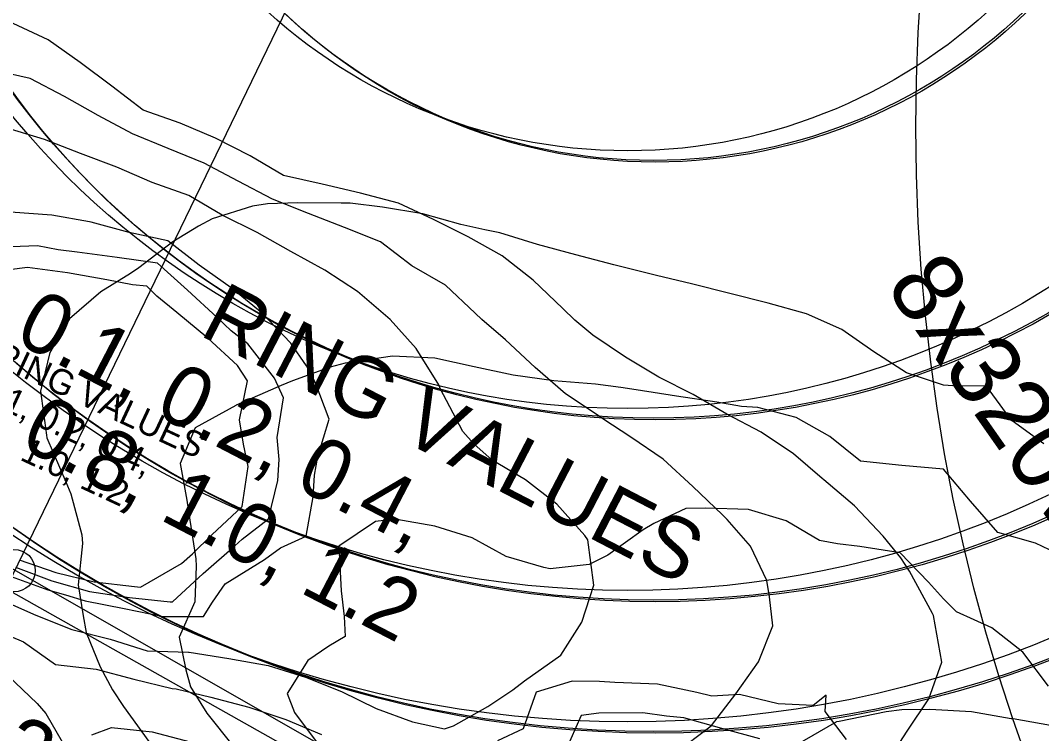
# Model space of a CAD drawing. Extents: x 1638506 to 1658005, y 834807 to 846788.
# Drawn here: x 1640509.7 to 1640711.8, y 842395.5 to 842536.6 of the extents above; entities that cross this region are included whole.
import ezdxf

# ---------------------------------------------------------------- set-up
doc = ezdxf.new("R2010")
doc.units = 0
for name, color, linetype in [('Default', 7, 'Continuous'), ('Old_Level_1', 7, 'Continuous'), ('Old_Level_2', 7, 'Continuous'), ('Old_Level_4', 7, 'Continuous'), ('Scratch_Level_0', 7, 'Continuous')]:
    doc.layers.add(name, color=color, linetype=linetype)

msp = doc.modelspace()

# ---------------------------------------------------------------- linework, layer by layer
at = {"layer": 'Default'}
msp.add_line((1640314.09, 842532.64), (1640637.56, 842350.59), dxfattribs=at)
at = {"layer": 'Old_Level_1'}
for points in [[(1640690.42, 842418.82), (1640690.18, 842419.27), (1640685.65, 842427.64), (1640683.96, 842430.27), (1640680.43, 842434.55), (1640674.78, 842440.54), (1640668.73, 842445.67), (1640668.39, 842445.97), (1640662.68, 842450.81), (1640656.27, 842455.16), (1640649.49, 842458.72), (1640642.86, 842462.61), (1640636.02, 842466.03), (1640629.42, 842469.97), (1640623, 842474.32), (1640619.41, 842477.26), (1640617.03, 842479.62), (1640611.2, 842485.22), (1640605.01, 842490.04), (1640598.31, 842493.77), (1640591.47, 842497.21), (1640584.54, 842500.44), (1640577.02, 842502.42), (1640569.42, 842504.21), (1640561.76, 842505.89), (1640555.14, 842509.81), (1640548.33, 842513.31), (1640541.28, 842516.27), (1640534.02, 842518.82), (1640527.82, 842523.61), (1640521.55, 842528.28), (1640515.2, 842532.77), (1640508.27, 842536)], [(1640658.59, 842416.78), (1640657.93, 842422.52), (1640657.41, 842425.77), (1640654.18, 842432.56), (1640649.57, 842437.87), (1640648.63, 842438.76), (1640642.79, 842444.36), (1640636.9, 842449.81), (1640630.48, 842454.15), (1640624.95, 842457.79), (1640624.03, 842458.42), (1640617.59, 842462.72), (1640611.58, 842467.93), (1640605.69, 842473.4), (1640601.01, 842477.39), (1640599.7, 842478.65), (1640593.84, 842484.19), (1640587.19, 842488.03), (1640580.96, 842492.76), (1640573.86, 842495.65), (1640566.71, 842498.42), (1640559.59, 842501.25), (1640552.79, 842504.77), (1640546.03, 842508.36), (1640538.93, 842511.24), (1640531.86, 842514.18), (1640525.11, 842517.82), (1640518.4, 842521.52), (1640511.62, 842525.09), (1640503.99, 842526.83)], [(1640621.97, 842433.85), (1640621.39, 842434.65), (1640615.86, 842440.9), (1640609.66, 842445.7), (1640603.04, 842449.61), (1640599.43, 842452.81), (1640597.25, 842455.28), (1640592.75, 842463.75), (1640592.51, 842464.47), (1640588.01, 842471.69), (1640582.88, 842477.41), (1640582.42, 842477.8), (1640576.39, 842482.97), (1640569.91, 842487.17), (1640563.21, 842490.9), (1640556.52, 842494.66), (1640549.65, 842498.04), (1640543.03, 842501.94), (1640535.79, 842504.5), (1640528.79, 842507.59), (1640521.61, 842510.3), (1640514.44, 842513.03), (1640507.06, 842515.3)], [(1640567.65, 842442.3), (1640567.88, 842446.61), (1640568.59, 842450.31), (1640570.82, 842457.71), (1640568.02, 842465.02), (1640566.31, 842468.25), (1640563.2, 842472.77), (1640557.51, 842478.68), (1640551.69, 842483.51), (1640551.42, 842483.72), (1640545.06, 842488.18), (1640538.85, 842492.96), (1640531.19, 842494.64), (1640523.68, 842496.65), (1640523.35, 842496.72), (1640515.91, 842498.08), (1640507.73, 842498.64)], [(1640560.65, 842445.57), (1640560.89, 842449.73), (1640560.48, 842454.09), (1640561.76, 842461.93), (1640559.96, 842465.83), (1640554.68, 842472.6), (1640551.43, 842475.19), (1640548.66, 842477.8), (1640542.74, 842483.2), (1640536.81, 842488.6), (1640528.87, 842489.67), (1640520.93, 842490.73), (1640517.14, 842491.18), (1640513.08, 842492), (1640504.49, 842491.7)], [(1640554.76, 842448.31), (1640553.86, 842452.76), (1640553.04, 842457.56), (1640554.61, 842465.27), (1640552.67, 842468.29), (1640546.77, 842473.75), (1640540.68, 842478.79), (1640536.67, 842482.07), (1640534.69, 842484.05), (1640531.9, 842484.3), (1640526.81, 842485.26), (1640519.04, 842486.68), (1640511.07, 842487.69), (1640507.5, 842487.23)], [(1640406.77, 842463.14), (1640413.31, 842459.07), (1640420.1, 842455.53), (1640427.02, 842452.26), (1640434.01, 842449.16), (1640440.59, 842445.17), (1640447.25, 842441.34), (1640453.59, 842436.84), (1640456.26, 842435.16), (1640460.09, 842432.67), (1640466.44, 842428.18), (1640472.25, 842422.54), (1640473.61, 842418.63), (1640476.35, 842413.25), (1640482.75, 842414.37), (1640485.31, 842414.35), (1640493.33, 842413.46), (1640499.55, 842408.7), (1640507.2, 842407), (1640513.04, 842401.41), (1640514.7, 842399.47), (1640517.95, 842393.85)], [(1640509.43, 842429.87), (1640516.69, 842427.34), (1640524.27, 842425.51), (1640532.29, 842424.6), (1640533.47, 842424.48), (1640541.55, 842429.15), (1640543.75, 842431.07), (1640547.56, 842434.79), (1640553.56, 842440.43), (1640554.76, 842448.31)], [(1640508.75, 842428.43), (1640515.94, 842425.74), (1640523.39, 842423.61), (1640531.27, 842422.41), (1640539.31, 842421.54), (1640539.77, 842421.54), (1640545.86, 842427.14), (1640552.15, 842432.65), (1640553.55, 842433.98), (1640558.82, 842437.98), (1640560.65, 842445.57)], [(1640507.89, 842426.57), (1640515.1, 842423.94), (1640518.61, 842422.97), (1640522.51, 842421.72), (1640530.25, 842420.22), (1640537.97, 842418.67), (1640545.92, 842418.67), (1640547.74, 842421.52), (1640550.24, 842425.1), (1640558.03, 842429.91), (1640561.19, 842432.27), (1640566.25, 842434.52), (1640567.65, 842442.3)], [(1640505.77, 842422.02), (1640512.77, 842418.94), (1640519.88, 842416.08), (1640527.44, 842414.19), (1640534.79, 842411.86), (1640542.97, 842411.61), (1640543.11, 842411.59), (1640550.96, 842410.33), (1640558.76, 842408.95), (1640566.13, 842406.67), (1640573.25, 842403.83), (1640580.12, 842400.47), (1640587.32, 842397.8), (1640593.64, 842396.42), (1640595.39, 842397.01), (1640602.21, 842400.87), (1640607.16, 842404.14), (1640609.49, 842405.91), (1640616.62, 842411.03), (1640620.81, 842417.52), (1640623.21, 842424.84), (1640621.97, 842433.85)], [(1640680.97, 842389.46), (1640685.17, 842395.95), (1640689.51, 842402.36), (1640692.08, 842409.6), (1640690.42, 842418.82)], [(1640639.59, 842391.88), (1640645.86, 842396.62), (1640646.47, 842397.11), (1640651.25, 842403.32), (1640655.79, 842409.65), (1640658.59, 842416.78)], [(1640503.25, 842416.62), (1640510.3, 842413.65), (1640516.64, 842409.14), (1640524.66, 842408.24), (1640532.17, 842406.23), (1640539.75, 842404.4), (1640540.5, 842404.32), (1640547.39, 842402.66), (1640554.92, 842400.71), (1640562.22, 842398.28), (1640569.28, 842395.32)], [(1640713.56, 842397.1), (1640706.19, 842398.37), (1640705.74, 842398.43), (1640697.92, 842399.77), (1640689.7, 842400.25), (1640684.15, 842400.2), (1640681.05, 842399.81), (1640671.72, 842397.9), (1640671.23, 842397.79), (1640663.1, 842393.14)], [(1640523.84, 842395.21), (1640527.71, 842396.68), (1640535.77, 842395.85), (1640543.29, 842393.88)]]:
    msp.add_lwpolyline(points, dxfattribs=at)
for centre, radius in [((1640635.3, 842614.58), 219), ((1640635.3, 842614.58), 193), ((1640635.3, 842614.58), 157), ((1640635.3, 842614.58), 106), ((1640508.42, 842427.72), 4.21)]:
    msp.add_circle(centre, radius, dxfattribs=at)
at = {"layer": 'Old_Level_2'}
for p, q in [((1640570.5, 842555.69), (1640460.25, 842328.04)), ((1640394.38, 842493.02), (1640843.22, 842236.75))]:
    msp.add_line(p, q, dxfattribs=at)
at = {"layer": 'Old_Level_4'}
for centre, radius in [((1641051.91, 842515.45), 365), ((1640629.86, 842616.81), 219), ((1640629.86, 842616.81), 193), ((1640629.86, 842616.81), 157), ((1640629.86, 842616.81), 106)]:
    msp.add_circle(centre, radius, dxfattribs=at)
at = {"layer": 'Scratch_Level_0'}
for points in [[(1640712.21, 842452.79), (1640705.99, 842457.4), (1640704.82, 842458.81), (1640700.9, 842464.2), (1640694.23, 842464.31), (1640692.41, 842464.45), (1640685.06, 842466.89), (1640678.59, 842471.03), (1640672.26, 842475.45), (1640665.24, 842478.53), (1640657.71, 842480.63), (1640650.09, 842482.55), (1640642.49, 842484.51), (1640635.61, 842486.13), (1640634.81, 842486.34), (1640627.17, 842488.22), (1640619.6, 842490.25), (1640612.03, 842492.27), (1640604.59, 842494.54), (1640601.59, 842495.19), (1640596.85, 842496.23), (1640589.31, 842498.3), (1640581.38, 842499.64), (1640574.94, 842500.41), (1640573.19, 842500.46), (1640564.6, 842500.52), (1640558.59, 842500.28), (1640555.63, 842499.85), (1640547.64, 842497.35), (1640544.96, 842495.9), (1640539.87, 842492.76), (1640533.15, 842487.63), (1640531.46, 842486.51), (1640525.62, 842482.92), (1640519.41, 842477.53), (1640515.54, 842470.92), (1640513.7, 842463.25), (1640514.84, 842454.52), (1640514.9, 842454.01), (1640518.68, 842445.3), (1640519.68, 842442.91), (1640521.84, 842434.79), (1640521.96, 842433.1), (1640521.14, 842424.91), (1640522.14, 842418.78), (1640522.73, 842415.46), (1640525.51, 842408.67), (1640527.93, 842404.14), (1640530.08, 842400.87), (1640535.1, 842393.94)], [(1640717.54, 842429.85), (1640710.62, 842433.13), (1640703.12, 842435.29), (1640697.71, 842441.46), (1640692.38, 842447.8), (1640684.13, 842448.51), (1640675.97, 842449.39), (1640669.89, 842454.29), (1640663.23, 842458.06), (1640655.61, 842460), (1640652.38, 842460.18), (1640647.53, 842461.04), (1640639.53, 842462.22), (1640631.58, 842463.52), (1640628.53, 842463.95), (1640623.53, 842464.61), (1640615.25, 842465.27), (1640607.22, 842466.41), (1640607.19, 842466.42), (1640599.47, 842468.08), (1640591.73, 842469.77), (1640583.36, 842470.17), (1640583.32, 842470.17), (1640573.99, 842468.81), (1640571.01, 842467.97), (1640563.54, 842465.28), (1640561.33, 842464.37), (1640552.41, 842460.47), (1640552.33, 842460.43), (1640544.3, 842455.98), (1640541.31, 842448.91), (1640542.64, 842441.64), (1640542.96, 842439.43), (1640544.38, 842430.07), (1640544.48, 842428.6), (1640544.2, 842421.55), (1640541.09, 842414.54), (1640542.44, 842408.08), (1640543.33, 842404.76), (1640546.62, 842399.52), (1640551.83, 842392.96)], [(1640713.17, 842404.85), (1640708.07, 842411.62), (1640701.94, 842416.41), (1640694.96, 842419.58), (1640692.36, 842422.17), (1640689.38, 842425.43), (1640683.79, 842431.26), (1640675.8, 842432.48), (1640671.42, 842433.05), (1640667.81, 842433.68), (1640661.21, 842437.57), (1640653.76, 842439.83), (1640645.28, 842440.11), (1640641.41, 842440.02), (1640635.07, 842437.03), (1640632.92, 842435.81), (1640625.97, 842430.8), (1640622.23, 842428.91), (1640614.56, 842428.1), (1640613.3, 842428.33), (1640605.82, 842430.52), (1640599.13, 842434.23), (1640591.71, 842436.55), (1640583.79, 842437.89), (1640579.98, 842437.45), (1640572.71, 842432.6), (1640573.2, 842423.73), (1640573.78, 842418.62), (1640573.96, 842414.71), (1640570.73, 842412.76), (1640566.58, 842409.92), (1640562.49, 842403.43), (1640563.93, 842399.66), (1640569.02, 842392.85)], [(1640673.2, 842394.28), (1640668.97, 842399.84), (1640669.14, 842403.06), (1640666.61, 842401.07), (1640659.63, 842401.34), (1640651.98, 842403.21), (1640646.56, 842402.86), (1640643.57, 842403.62), (1640635.81, 842405.27), (1640627.34, 842405.56), (1640624.32, 842405.79), (1640618.87, 842405.85), (1640611.77, 842403.69), (1640609.17, 842396.42), (1640604.11, 842394.02)], [(1640656.06, 842394.46), (1640648.48, 842396.48), (1640640.97, 842398.62), (1640637.54, 842398.93), (1640632.87, 842399.62), (1640624.19, 842399.49), (1640620.69, 842399.06), (1640617.54, 842392.08)]]:
    msp.add_lwpolyline(points, dxfattribs=at)
for radius in [219, 193, 157, 106]:
    msp.add_circle((1640634.95, 842614.89), radius, dxfattribs=at)

# ---------------------------------------------------------------- texts
at = {"layer": 'Old_Level_1'}
for s, height, rotation, p in [('8x320W LED Fixtures', 14, 305, (1640680.68, 842484.01)), ('RING VALUES', 5, 335, (1640503.95, 842468.81)), ('0.1, 0.2, 0.4,', 5, 335, (1640500.78, 842462.02)), ('0.8, 1.0, 1.2', 5, 335, (1640497.61, 842455.22)), ('GE ERL2x23B340', 8, 335, (1640444.98, 842410.94))]:
    msp.add_text(s, height=height, rotation=rotation, dxfattribs=at).set_placement(p)
at = {"layer": 'Scratch_Level_0'}
for s, p in [('RING VALUES', (1640544.83, 842474.46)), ('0.1, 0.2, 0.4,', (1640508.16, 842473.23)), ('0.8, 1.0, 1.2', (1640509.24, 842452.38)), ('GE ERL2x23C340', (1640452.16, 842416.2))]:
    msp.add_text(s, height=12, rotation=332.5519, dxfattribs=at).set_placement(p)

doc.saveas('drawing.dxf')
